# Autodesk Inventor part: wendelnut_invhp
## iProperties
Created: 2005-05
Part Number: wendelnut_invhp
Cost Center: 0,013 kg
Document SubType Name: Modeling
Designer: Administrator
Authority: 13191 mm^3
SaveDate: 2005-05-29
SaveTime: 15:41
TotalMass: 0,013 kg
TotalVolume: 13191 mm^3
Author: Administrator
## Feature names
1. Extrusion1
2. Bohrung1 [Hole]
3. Trennen1
4. Erhebung1
5. Spiegeln1 [Mirror]
